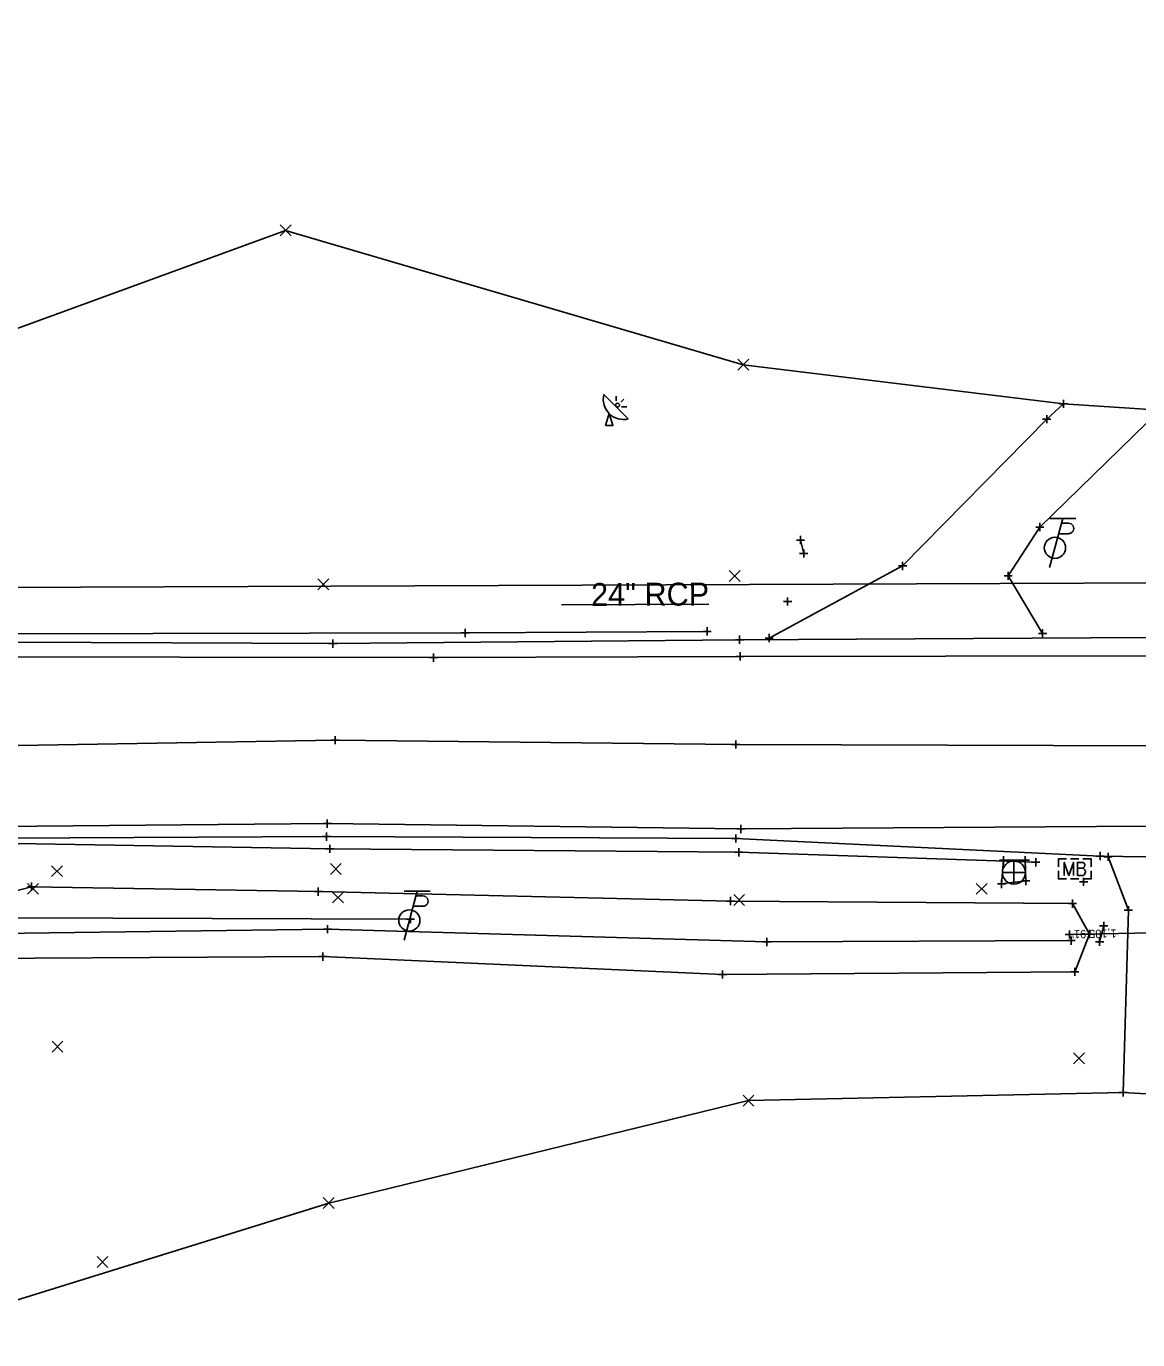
# Model space of a CAD drawing. Extents: x 2319153 to 2321514, y 575338 to 575500.
# Drawn here: x 2320825.9 to 2320961.9, y 575339 to 575499.6 of the extents above; entities that cross this region are included whole.
import ezdxf

# ---------------------------------------------------------------- set-up
doc = ezdxf.new("R2010")
doc.units = 0
for name, color, linetype in [('DR_X_Ditch', 7, 'Continuous'), ('DR_X_Elev_Flow', 7, 'Continuous'), ('DR_X_Storm_Sewer', 7, 'Continuous'), ('DR_X_Text', 7, 'Continuous'), ('PV_X_COP', 7, 'Continuous'), ('PV_X_Driveway', 7, 'Continuous'), ('PV_X_EOP', 7, 'Continuous'), ('PV_X_Shoulder', 7, 'Continuous'), ('RD_X_Cells', 7, 'Continuous'), ('RD_X_Concrete_Pad', 7, 'Continuous'), ('RD_X_GR_Lt', 7, 'Continuous'), ('SC_Scratch1', 7, 'Continuous'), ('SV_X_Break_Lines', 7, 'Continuous'), ('SV_X_Control_Cells_Found', 7, 'Continuous'), ('SV_X_Random_Point', 7, 'Continuous'), ('SV_X_Shot_Marker', 7, 'Continuous'), ('SV_X_Terrain_Boundary', 7, 'Continuous'), ('UT_X_Misc_Cells', 7, 'Continuous'), ('UT_X_Telecom', 7, 'Continuous')]:
    doc.layers.add(name, color=color, linetype=linetype)

msp = doc.modelspace()

# ---------------------------------------------------------------- linework, layer by layer
at = {"layer": 'DR_X_Ditch'}
msp.add_lwpolyline([(2320953.76, 575387.79), (2320916.54, 575387.63), (2320862.79, 575389.2), (2320819.49, 575388.61)], dxfattribs=at)
at = {"layer": 'DR_X_Elev_Flow'}
for p, q in [((2320953.03, 575388.55), (2320954.03, 575388.55)), ((2320953.53, 575389.05), (2320953.53, 575388.05)), ((2320953.53, 575388.55), (2320953.53, 575388.55))]:
    msp.add_line(p, q, dxfattribs=at)
at = {"layer": 'DR_X_Storm_Sewer'}
for p, q in [((2320984.73, 575431.64), (2320820.1, 575430.96)), ((2320997.8, 575389.45), (2320953.53, 575388.55))]:
    msp.add_line(p, q, dxfattribs=at)
at = {"layer": 'DR_X_Text'}
msp.add_line((2320891.4, 575428.86), (2320909.45, 575428.93), dxfattribs=at)
at = {"layer": 'PV_X_COP'}
msp.add_lwpolyline([(2320664.58, 575411.98), (2320714.9, 575412.38), (2320764.67, 575412.55), (2320812.81, 575411.44), (2320863.71, 575412.31), (2320912.72, 575411.78), (2321003.29, 575411.48), (2321063.97, 575411.74), (2321113.08, 575411.94), (2321163.31, 575411.56), (2321212.82, 575411.61), (2321262.91, 575411.78), (2321313.37, 575411.56), (2321362.17, 575411.58), (2321412.59, 575412.78), (2321463.09, 575413.59), (2321512.4, 575413.87)], dxfattribs=at)
at = {"layer": 'PV_X_Driveway'}
for points in [[(2320916.81, 575424.8), (2320933.14, 575433.62), (2320950.76, 575451.57), (2320952.83, 575453.45)], [(2320964.59, 575452.67), (2320949.93, 575438.38), (2320946.04, 575432.42), (2320950.26, 575425.38)], [(2320958.26, 575398.05), (2320960.75, 575391.52), (2320960.12, 575369.23)]]:
    msp.add_lwpolyline(points, dxfattribs=at)
at = {"layer": 'PV_X_EOP'}
for points in [[(2320664.7, 575422.48), (2320715.11, 575422.41), (2320765.04, 575422.04), (2320813.73, 575422.51), (2320875.77, 575422.41), (2320913.27, 575422.56), (2320963.52, 575422.63), (2321012.62, 575422.4), (2321063.13, 575422.74), (2321112.87, 575422.46), (2321162.94, 575422.5), (2321212.67, 575422.22), (2321263.07, 575422.64), (2321312.9, 575422.52), (2321362.03, 575422.99), (2321412.61, 575423.24), (2321462.61, 575423.66), (2321512.13, 575424.2)], [(2321512.27, 575403.63), (2321462.49, 575403.2), (2321412.87, 575402.74), (2321362.69, 575401.87), (2321312.5, 575402.02), (2321262.43, 575401.63), (2321211.98, 575401.55), (2321107.93, 575402.06), (2321016.27, 575401.73), (2320963.04, 575401.8), (2320913.34, 575401.45), (2320862.76, 575402.1), (2320813.85, 575401.67), (2320764.22, 575401.77), (2320714.4, 575401.87), (2320664.35, 575401.67)]]:
    msp.add_lwpolyline(points, dxfattribs=at)
at = {"layer": 'PV_X_Shoulder'}
for points in [[(2320664.52, 575424.33), (2320715.19, 575424.71), (2320764.98, 575424.15), (2320814.14, 575424.35), (2320863.42, 575424.12), (2320913.2, 575424.6), (2320963.28, 575424.88), (2321012.77, 575424.72), (2321063.18, 575424.45), (2321113.13, 575424.68), (2321162.73, 575424.41), (2321212.81, 575424.31), (2321262.9, 575424.09), (2321312.43, 575424.58), (2321362.34, 575425.06), (2321412.6, 575426.1), (2321462.14, 575426.29), (2321512.24, 575426.46)], [(2321513.03, 575401.02), (2321462.24, 575401.09), (2321412.23, 575401.08), (2321362.25, 575400.75), (2321312.5, 575400.39), (2321262.08, 575400.08), (2321212.3, 575399.81), (2321130.87, 575399.59), (2321095.99, 575399.76), (2321032.33, 575399.84), (2320996.03, 575397.56), (2320957.29, 575398.14), (2320912.73, 575400.28), (2320862.68, 575400.51), (2320815.54, 575400.3), (2320764.25, 575400.14), (2320714.58, 575400.4), (2320664.56, 575400.05)]]:
    msp.add_lwpolyline(points, dxfattribs=at)
at = {"layer": 'RD_X_Cells'}
for p, q in [((2320899.57, 575451.6), (2320896.59, 575454.58)), ((2320898.1, 575453.8), (2320898.1, 575454.39)), ((2320898.67, 575453.67), (2320899.02, 575454.01)), ((2320898.74, 575453.1), (2320899.39, 575453.1)), ((2320953.68, 575397.79), (2320954.69, 575397.79)), ((2320954.2, 575396.57), (2320954.2, 575396.57)), ((2320953.68, 575395.35), (2320954.69, 575395.35))]:
    msp.add_line(p, q, dxfattribs=at)
msp.add_lwpolyline([(2320896.79, 575450.81), (2320897.69, 575450.81), (2320897.24, 575452.26)], close=True, dxfattribs=at)
for points in [[(2320952.2, 575396.82), (2320952.2, 575397.79), (2320953.17, 575397.79)], [(2320955.2, 575397.79), (2320956.2, 575397.79), (2320956.2, 575396.82)], [(2320953.17, 575395.35), (2320952.2, 575395.35), (2320952.2, 575396.32)], [(2320952.9, 575395.77), (2320952.9, 575397.37), (2320953.48, 575395.77), (2320954.03, 575397.37), (2320954.03, 575395.77)], [(2320955.22, 575396.64), (2320955.28, 575396.7), (2320955.32, 575396.74), (2320955.34, 575396.77), (2320955.36, 575396.8), (2320955.38, 575396.85), (2320955.39, 575396.89), (2320955.42, 575396.98), (2320955.42, 575397.01), (2320955.42, 575397.06), (2320955.41, 575397.14), (2320955.38, 575397.2), (2320955.34, 575397.25), (2320955.28, 575397.3), (2320955.23, 575397.33), (2320955.2, 575397.34), (2320955.14, 575397.37), (2320954.52, 575397.37), (2320954.52, 575395.77), (2320955.22, 575395.77), (2320955.31, 575395.82), (2320955.38, 575395.88), (2320955.44, 575395.98), (2320955.48, 575396.09), (2320955.49, 575396.21), (2320955.49, 575396.28), (2320955.47, 575396.36), (2320955.42, 575396.47), (2320955.36, 575396.55), (2320955.22, 575396.64), (2320954.52, 575396.64)], [(2320956.2, 575396.32), (2320956.2, 575395.35), (2320955.2, 575395.35)]]:
    msp.add_lwpolyline(points, dxfattribs=at)
msp.add_circle((2320898.26, 575453.29), 0.243, dxfattribs=at)
msp.add_arc((2320898.99, 575454), 2.47, 166.3356, 283.6673, dxfattribs=at)
at = {"layer": 'RD_X_Concrete_Pad'}
msp.add_lwpolyline([(2320948.19, 575395.09), (2320945.25, 575394.72), (2320945.47, 575397.62), (2320948.14, 575397.64)], close=True, dxfattribs=at)
at = {"layer": 'RD_X_GR_Lt'}
for p, q in [((2320921.04, 575435.14), (2320920.65, 575436.79)), ((2320813.7, 575425.29), (2320879.64, 575425.43)), ((2320879.64, 575425.43), (2320909.22, 575425.62)), ((2320863.05, 575399.02), (2320814.09, 575399.86)), ((2320913.1, 575398.6), (2320863.05, 575399.02)), ((2320949.42, 575397.38), (2320913.1, 575398.6)), ((2320957.24, 575387.64), (2320957.74, 575389.59))]:
    msp.add_line(p, q, dxfattribs=at)
at = {"layer": 'SV_X_Break_Lines'}
msp.add_lwpolyline([(2320821.03, 575342.66), (2320819.85, 575385.62), (2320862.23, 575385.84), (2320911.12, 575383.65), (2320954.21, 575383.98), (2320955.99, 575388.6), (2320953.91, 575392.32), (2320912.09, 575392.64), (2320861.66, 575393.79), (2320826.59, 575394.39), (2320820.03, 575392.72)], dxfattribs=at)
at = {"layer": 'SV_X_Control_Cells_Found'}
for p, q in [((2320945.34, 575396.12), (2320948.16, 575396.12)), ((2320946.75, 575397.53), (2320946.75, 575394.71))]:
    msp.add_line(p, q, dxfattribs=at)
msp.add_circle((2320946.75, 575396.12), 1.41, dxfattribs=at)
at = {"layer": 'SV_X_Random_Point'}
for p, q in [((2320857, 575474.01), (2320858.33, 575475.34)), ((2320857, 575475.34), (2320858.33, 575474.01)), ((2320912.97, 575457.56), (2320914.31, 575458.9)), ((2320912.97, 575458.9), (2320914.31, 575457.56)), ((2320911.93, 575431.71), (2320913.27, 575433.05)), ((2320911.93, 575433.05), (2320913.27, 575431.71)), ((2320861.62, 575430.69), (2320862.95, 575432.03)), ((2320861.62, 575432.03), (2320862.95, 575430.69)), ((2320829.03, 575395.63), (2320830.36, 575396.96)), ((2320829.03, 575396.96), (2320830.36, 575395.63)), ((2320863.13, 575395.9), (2320864.46, 575397.23)), ((2320863.13, 575397.23), (2320864.46, 575395.9)), ((2320826.1, 575393.46), (2320827.43, 575394.79)), ((2320826.1, 575394.79), (2320827.43, 575393.46)), ((2320942.13, 575393.46), (2320943.46, 575394.8)), ((2320942.13, 575394.8), (2320943.46, 575393.46)), ((2320863.41, 575392.41), (2320864.74, 575393.74)), ((2320863.41, 575393.74), (2320864.74, 575392.41)), ((2320912.47, 575392.1), (2320913.8, 575393.44)), ((2320912.47, 575393.44), (2320913.8, 575392.1)), ((2320829.09, 575374.16), (2320830.42, 575375.5)), ((2320829.09, 575375.5), (2320830.42, 575374.16)), ((2320954.05, 575372.74), (2320955.39, 575374.07)), ((2320954.05, 575374.07), (2320955.39, 575372.74)), ((2320913.62, 575367.55), (2320914.95, 575368.88)), ((2320913.62, 575368.88), (2320914.95, 575367.55)), ((2320862.27, 575355.03), (2320863.6, 575356.37)), ((2320862.27, 575356.37), (2320863.6, 575355.03)), ((2320834.59, 575347.82), (2320835.93, 575349.15)), ((2320834.59, 575349.15), (2320835.93, 575347.82))]:
    msp.add_line(p, q, dxfattribs=at)
at = {"layer": 'SV_X_Shot_Marker'}
for p, q in [((2320952.83, 575453.95), (2320952.83, 575452.95)), ((2320952.33, 575453.45), (2320953.33, 575453.45)), ((2320952.83, 575453.45), (2320952.83, 575453.45)), ((2320950.26, 575451.57), (2320951.26, 575451.57)), ((2320950.76, 575452.07), (2320950.76, 575451.07)), ((2320950.76, 575451.57), (2320950.76, 575451.57)), ((2320949.43, 575438.38), (2320950.43, 575438.38)), ((2320949.93, 575438.88), (2320949.93, 575437.88)), ((2320949.93, 575438.38), (2320949.93, 575438.38)), ((2320920.15, 575436.79), (2320921.15, 575436.79)), ((2320920.65, 575437.29), (2320920.65, 575436.29)), ((2320920.65, 575436.79), (2320920.65, 575436.79)), ((2320920.54, 575435.14), (2320921.54, 575435.14)), ((2320921.04, 575435.64), (2320921.04, 575434.64)), ((2320921.04, 575435.14), (2320921.04, 575435.14)), ((2320932.64, 575433.62), (2320933.64, 575433.62)), ((2320933.14, 575434.12), (2320933.14, 575433.12)), ((2320933.14, 575433.62), (2320933.14, 575433.62)), ((2320945.54, 575432.42), (2320946.54, 575432.42)), ((2320946.04, 575432.92), (2320946.04, 575431.92)), ((2320946.04, 575432.42), (2320946.04, 575432.42)), ((2320918.57, 575429.27), (2320919.57, 575429.27)), ((2320919.07, 575429.77), (2320919.07, 575428.77)), ((2320919.07, 575429.27), (2320919.07, 575429.27)), ((2320879.14, 575425.43), (2320880.14, 575425.43)), ((2320879.64, 575425.93), (2320879.64, 575424.93)), ((2320879.64, 575425.43), (2320879.64, 575425.43)), ((2320908.72, 575425.62), (2320909.72, 575425.62)), ((2320909.22, 575426.12), (2320909.22, 575425.12)), ((2320909.22, 575425.62), (2320909.22, 575425.62)), ((2320913.2, 575425.1), (2320913.2, 575424.1)), ((2320916.81, 575425.3), (2320916.81, 575424.3)), ((2320949.76, 575425.38), (2320950.76, 575425.38)), ((2320950.26, 575425.88), (2320950.26, 575424.88)), ((2320950.26, 575425.38), (2320950.26, 575425.38)), ((2320862.92, 575424.12), (2320863.92, 575424.12)), ((2320863.42, 575424.62), (2320863.42, 575423.62)), ((2320863.42, 575424.12), (2320863.42, 575424.12)), ((2320912.7, 575424.6), (2320913.7, 575424.6)), ((2320913.2, 575424.6), (2320913.2, 575424.6)), ((2320916.31, 575424.8), (2320917.31, 575424.8)), ((2320916.81, 575424.8), (2320916.81, 575424.8)), ((2320875.27, 575422.41), (2320876.27, 575422.41)), ((2320875.77, 575422.91), (2320875.77, 575421.91)), ((2320875.77, 575422.41), (2320875.77, 575422.41)), ((2320912.77, 575422.56), (2320913.77, 575422.56)), ((2320913.27, 575423.06), (2320913.27, 575422.06)), ((2320913.27, 575422.56), (2320913.27, 575422.56)), ((2320863.21, 575412.31), (2320864.21, 575412.31)), ((2320863.71, 575412.81), (2320863.71, 575411.81)), ((2320863.71, 575412.31), (2320863.71, 575412.31)), ((2320912.72, 575412.28), (2320912.72, 575411.28)), ((2320912.22, 575411.78), (2320913.22, 575411.78)), ((2320912.72, 575411.78), (2320912.72, 575411.78)), ((2320862.76, 575402.6), (2320862.76, 575401.6)), ((2320862.26, 575402.1), (2320863.26, 575402.1)), ((2320862.68, 575401.01), (2320862.68, 575400.01)), ((2320862.76, 575402.1), (2320862.76, 575402.1)), ((2320912.84, 575401.45), (2320913.84, 575401.45)), ((2320913.34, 575401.95), (2320913.34, 575400.95)), ((2320913.34, 575401.45), (2320913.34, 575401.45)), ((2320862.18, 575400.51), (2320863.18, 575400.51)), ((2320862.68, 575400.51), (2320862.68, 575400.51)), ((2320863.05, 575399.52), (2320863.05, 575398.52)), ((2320912.23, 575400.28), (2320913.23, 575400.28)), ((2320912.73, 575400.78), (2320912.73, 575399.78)), ((2320912.73, 575400.28), (2320912.73, 575400.28)), ((2320862.55, 575399.02), (2320863.55, 575399.02)), ((2320863.05, 575399.02), (2320863.05, 575399.02)), ((2320912.6, 575398.6), (2320913.6, 575398.6)), ((2320913.1, 575399.1), (2320913.1, 575398.1)), ((2320913.1, 575398.6), (2320913.1, 575398.6)), ((2320945.47, 575398.12), (2320945.47, 575397.12)), ((2320948.14, 575398.14), (2320948.14, 575397.14)), ((2320949.42, 575397.88), (2320949.42, 575396.88)), ((2320956.79, 575398.14), (2320957.79, 575398.14)), ((2320957.29, 575398.64), (2320957.29, 575397.64)), ((2320957.29, 575398.14), (2320957.29, 575398.14)), ((2320957.76, 575398.05), (2320958.76, 575398.05)), ((2320958.26, 575398.55), (2320958.26, 575397.55)), ((2320958.26, 575398.05), (2320958.26, 575398.05)), ((2320944.97, 575397.62), (2320945.97, 575397.62)), ((2320945.47, 575397.62), (2320945.47, 575397.62)), ((2320947.64, 575397.64), (2320948.64, 575397.64)), ((2320948.14, 575397.64), (2320948.14, 575397.64)), ((2320948.92, 575397.38), (2320949.92, 575397.38)), ((2320949.42, 575397.38), (2320949.42, 575397.38)), ((2320826.59, 575394.89), (2320826.59, 575393.89)), ((2320944.75, 575394.72), (2320945.75, 575394.72)), ((2320945.25, 575395.22), (2320945.25, 575394.22)), ((2320945.25, 575394.72), (2320945.25, 575394.72)), ((2320947.69, 575395.09), (2320948.69, 575395.09)), ((2320948.19, 575395.59), (2320948.19, 575394.59)), ((2320948.19, 575395.09), (2320948.19, 575395.09)), ((2320954.78, 575394.99), (2320955.78, 575394.99)), ((2320955.28, 575395.49), (2320955.28, 575394.49)), ((2320955.28, 575394.99), (2320955.28, 575394.99)), ((2320826.09, 575394.39), (2320827.09, 575394.39)), ((2320826.59, 575394.39), (2320826.59, 575394.39)), ((2320861.16, 575393.79), (2320862.16, 575393.79)), ((2320861.66, 575394.29), (2320861.66, 575393.29)), ((2320861.66, 575393.79), (2320861.66, 575393.79)), ((2320912.09, 575393.14), (2320912.09, 575392.14)), ((2320911.59, 575392.64), (2320912.59, 575392.64)), ((2320912.09, 575392.64), (2320912.09, 575392.64)), ((2320953.41, 575392.32), (2320954.41, 575392.32)), ((2320953.91, 575392.82), (2320953.91, 575391.82)), ((2320953.91, 575392.32), (2320953.91, 575392.32)), ((2320960.25, 575391.52), (2320961.25, 575391.52)), ((2320960.75, 575392.02), (2320960.75, 575391.02)), ((2320960.75, 575391.52), (2320960.75, 575391.52)), ((2320862.79, 575389.7), (2320862.79, 575388.7)), ((2320872.43, 575390.42), (2320873.43, 575390.42)), ((2320872.93, 575390.92), (2320872.93, 575389.92)), ((2320872.93, 575390.42), (2320872.93, 575390.42)), ((2320957.74, 575390.09), (2320957.74, 575389.09)), ((2320862.29, 575389.2), (2320863.29, 575389.2)), ((2320862.79, 575389.2), (2320862.79, 575389.2)), ((2320916.54, 575388.13), (2320916.54, 575387.13)), ((2320953.76, 575388.29), (2320953.76, 575387.29)), ((2320955.49, 575388.6), (2320956.49, 575388.6)), ((2320955.99, 575389.1), (2320955.99, 575388.1)), ((2320955.99, 575388.6), (2320955.99, 575388.6)), ((2320957.24, 575389.59), (2320958.24, 575389.59)), ((2320957.24, 575388.14), (2320957.24, 575387.14)), ((2320957.74, 575389.59), (2320957.74, 575389.59)), ((2320916.04, 575387.63), (2320917.04, 575387.63)), ((2320916.54, 575387.63), (2320916.54, 575387.63)), ((2320953.26, 575387.79), (2320954.26, 575387.79)), ((2320953.76, 575387.79), (2320953.76, 575387.79)), ((2320956.74, 575387.64), (2320957.74, 575387.64)), ((2320957.24, 575387.64), (2320957.24, 575387.64)), ((2320861.73, 575385.84), (2320862.73, 575385.84)), ((2320862.23, 575386.34), (2320862.23, 575385.34)), ((2320862.23, 575385.84), (2320862.23, 575385.84)), ((2320910.62, 575383.65), (2320911.62, 575383.65)), ((2320911.12, 575384.15), (2320911.12, 575383.15)), ((2320911.12, 575383.65), (2320911.12, 575383.65)), ((2320953.71, 575383.98), (2320954.71, 575383.98)), ((2320954.21, 575384.48), (2320954.21, 575383.48)), ((2320954.21, 575383.98), (2320954.21, 575383.98)), ((2320959.62, 575369.23), (2320960.62, 575369.23)), ((2320960.12, 575369.73), (2320960.12, 575368.73)), ((2320960.12, 575369.23), (2320960.12, 575369.23))]:
    msp.add_line(p, q, dxfattribs=at)
at = {"layer": 'SV_X_Terrain_Boundary'}
for points in [[(2321262.9, 575424.09), (2321213.75, 575454.03), (2321174.26, 575455.72), (2321165.44, 575454.44), (2321113.51, 575450.31), (2321063.39, 575450.45), (2321013.2, 575451.03), (2320972.82, 575455.47), (2320964.59, 575452.67), (2320952.83, 575453.45), (2320913.64, 575458.23), (2320857.66, 575474.67), (2320815.41, 575459.23), (2320777.59, 575499.63), (2320770.49, 575484.86), (2320769.15, 575483.51), (2320759.85, 575485.4), (2320758.6, 575484.73), (2320747.1, 575477.92), (2320738.56, 575481.4), (2320734.01, 575484.3), (2320722.62, 575480.62), (2320707.74, 575483.24), (2320663.9, 575465.47)], [(2320654.2, 575376.01), (2320714.52, 575366.13), (2320764.01, 575354.08), (2320802.52, 575338.98), (2320810.61, 575341.7), (2320812.62, 575342.69), (2320818.49, 575343.02), (2320821.03, 575342.66), (2320862.94, 575355.7), (2320914.29, 575368.22), (2320960.12, 575369.23), (2320978.33, 575368.17), (2321013.4, 575370.96), (2321062.8, 575369.91), (2321112.71, 575370.23), (2321163.35, 575371.72), (2321212.47, 575372.75), (2321262.08, 575400.08)]]:
    msp.add_lwpolyline(points, dxfattribs=at)
at = {"layer": 'UT_X_Misc_Cells'}
for p, q in [((2320952.73, 575439.44), (2320951.12, 575433.44)), ((2320954.33, 575439.44), (2320951.13, 575439.44)), ((2320952.57, 575438.84), (2320953.42, 575438.84)), ((2320952.23, 575437.57), (2320953.42, 575437.57)), ((2320873.76, 575393.86), (2320872.15, 575387.86)), ((2320875.36, 575393.86), (2320872.16, 575393.86)), ((2320873.6, 575393.26), (2320874.45, 575393.26)), ((2320873.26, 575391.99), (2320874.45, 575391.99))]:
    msp.add_line(p, q, dxfattribs=at)
for centre in [(2320951.77, 575435.84), (2320872.79, 575390.26)]:
    msp.add_circle(centre, 1.3, dxfattribs=at)
for centre in [(2320953.43, 575438.21), (2320874.46, 575392.63)]:
    msp.add_arc(centre, 0.638, 268.8767, 91.1233, dxfattribs=at)
at = {"layer": 'UT_X_Telecom'}
msp.add_lwpolyline([(2320702.96, 575391), (2320872.93, 575390.42)], dxfattribs=at)

# ---------------------------------------------------------------- texts
at = {"layer": 'DR_X_Text'}
msp.add_text('24" RCP', height=2.8, rotation=0.2376, dxfattribs=at).set_placement((2320895.03, 575428.73))
at = {"layer": 'SC_Scratch1'}
msp.add_text("1,185.91'", height=1, rotation=181.1633, dxfattribs=at).set_placement((2320959.3, 575389.17))

doc.saveas('drawing.dxf')
